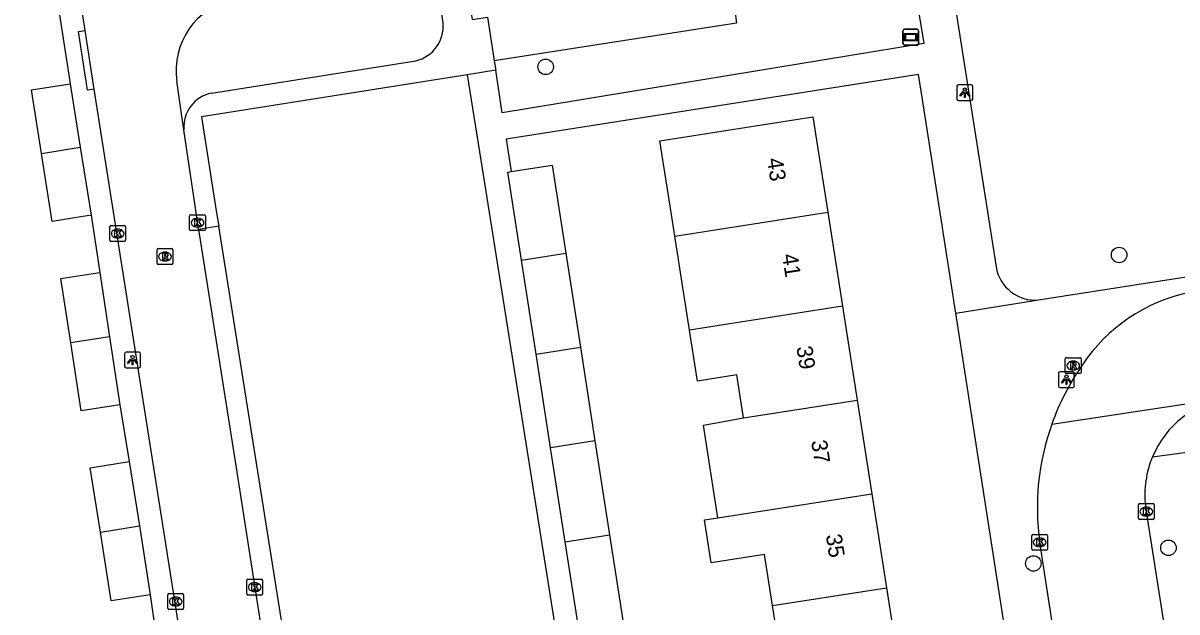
# Model space of a CAD drawing. Extents: x 160077 to 160945, y 386481 to 387498.
# Drawn here: x 160547.5 to 160620.3, y 387416.6 to 387453.8 of the extents above; entities that cross this region are included whole.
import ezdxf

# ---------------------------------------------------------------- set-up
doc = ezdxf.new("R2010")
doc.units = 0
for name, color, linetype in [('IMGEO_Boom', 7, 'Continuous'), ('IMGEO_Groenvoorziening', 7, 'Continuous'), ('IMGEO_Kolk', 7, 'Continuous'), ('IMGEO_Lichtpunt', 7, 'Continuous'), ('IMGEO_Pand', 7, 'Continuous'), ('IMGEO_Pand_nummerreeks', 7, 'Continuous'), ('IMGEO_Rijbaan_lokaal_open', 7, 'Continuous'), ('IMGEO_Rioolput', 7, 'Continuous'), ('IMGEO_Verklikker', 7, 'Continuous'), ('IMGEO_Voetpad_open', 7, 'Continuous')]:
    doc.layers.add(name, color=color, linetype=linetype)

msp = doc.modelspace()

# ---------------------------------------------------------------- linework, layer by layer
at = {"layer": 'IMGEO_Boom'}
for centre in [(160580.467, 387451.067), (160616.653, 387439.186), (160619.768, 387420.692), (160611.243, 387419.704)]:
    msp.add_circle(centre, 0.489, dxfattribs=at)
at = {"layer": 'IMGEO_Groenvoorziening'}
msp.add_lwpolyline([(160525.051, 387462.081), (160541.077, 387464.558), (160541.983, 387470.387), (160543.017, 387477.036), (160575.946, 387480.154), (160584.088, 387468.697), (160592.027, 387457.524), (160592.503, 387453.837), (160577.226, 387451.446)], dxfattribs=at)
at = {"layer": 'IMGEO_Kolk'}
for p, q in [((160557.998, 387440.804), (160557.998, 387441.656)), ((160558.073, 387441.73), (160558.925, 387441.73)), ((160558.999, 387441.656), (160558.999, 387440.804)), ((160552.962, 387440.113), (160552.962, 387440.965)), ((160553.037, 387441.039), (160553.889, 387441.039)), ((160553.963, 387440.965), (160553.963, 387440.113)), ((160558.509, 387440.95), (160558.484, 387440.95)), ((160558.486, 387441.51), (160558.511, 387441.51)), ((160553.473, 387440.259), (160553.448, 387440.259)), ((160553.45, 387440.819), (160553.475, 387440.819)), ((160558.925, 387440.73), (160558.073, 387440.73)), ((160553.889, 387440.039), (160553.037, 387440.039)), ((160617.871, 387422.556), (160617.871, 387423.408)), ((160617.946, 387423.482), (160618.798, 387423.482)), ((160618.872, 387423.408), (160618.872, 387422.556)), ((160618.382, 387422.702), (160618.357, 387422.702)), ((160618.359, 387423.262), (160618.384, 387423.262)), ((160618.798, 387422.482), (160617.946, 387422.482)), ((160611.139, 387420.614), (160611.139, 387421.466)), ((160611.214, 387421.54), (160612.066, 387421.54)), ((160611.627, 387421.32), (160611.652, 387421.32)), ((160612.14, 387421.466), (160612.14, 387420.614)), ((160612.066, 387420.54), (160611.214, 387420.54)), ((160611.65, 387420.76), (160611.625, 387420.76)), ((160561.606, 387417.779), (160561.606, 387418.631)), ((160561.681, 387418.705), (160562.533, 387418.705)), ((160562.094, 387418.485), (160562.119, 387418.485)), ((160562.607, 387418.631), (160562.607, 387417.779)), ((160556.621, 387416.871), (160556.621, 387417.723)), ((160556.696, 387417.797), (160557.548, 387417.797)), ((160557.109, 387417.577), (160557.134, 387417.577)), ((160557.622, 387417.723), (160557.622, 387416.871)), ((160562.533, 387417.705), (160561.681, 387417.705)), ((160562.117, 387417.925), (160562.092, 387417.925)), ((160557.132, 387417.017), (160557.107, 387417.017)), ((160557.548, 387416.797), (160556.696, 387416.797))]:
    msp.add_line(p, q, dxfattribs=at)
for points in [[(160557.998, 387440.804), (160557.998, 387441.656)], [(160558.073, 387441.73), (160558.925, 387441.73)], [(160558.999, 387441.656), (160558.999, 387440.804)], [(160552.962, 387440.113), (160552.962, 387440.965)], [(160553.037, 387441.039), (160553.889, 387441.039)], [(160553.963, 387440.965), (160553.963, 387440.113)], [(160558.319, 387441.43), (160558.442, 387441.43), (160558.442, 387441.279), (160558.572, 387441.43), (160558.736, 387441.43), (160558.59, 387441.279), (160558.743, 387441.03), (160558.591, 387441.03), (160558.506, 387441.194), (160558.442, 387441.127), (160558.442, 387441.03), (160558.319, 387441.03), (160558.319, 387441.43)], [(160553.283, 387440.739), (160553.406, 387440.739), (160553.406, 387440.588), (160553.536, 387440.739), (160553.7, 387440.739), (160553.554, 387440.588), (160553.707, 387440.339), (160553.555, 387440.339), (160553.47, 387440.503), (160553.406, 387440.436), (160553.406, 387440.339), (160553.283, 387440.339), (160553.283, 387440.739)], [(160558.925, 387440.73), (160558.073, 387440.73)], [(160553.889, 387440.039), (160553.037, 387440.039)], [(160617.871, 387422.556), (160617.871, 387423.408)], [(160617.946, 387423.482), (160618.798, 387423.482)], [(160618.872, 387423.408), (160618.872, 387422.556)], [(160618.192, 387423.182), (160618.315, 387423.182), (160618.315, 387423.031), (160618.445, 387423.182), (160618.609, 387423.182), (160618.463, 387423.031), (160618.616, 387422.782), (160618.464, 387422.782), (160618.379, 387422.946), (160618.315, 387422.879), (160618.315, 387422.782), (160618.192, 387422.782), (160618.192, 387423.182)], [(160618.798, 387422.482), (160617.946, 387422.482)], [(160611.139, 387420.614), (160611.139, 387421.466)], [(160611.214, 387421.54), (160612.066, 387421.54)], [(160611.46, 387421.24), (160611.583, 387421.24), (160611.583, 387421.089), (160611.713, 387421.24), (160611.877, 387421.24), (160611.731, 387421.089), (160611.884, 387420.84), (160611.732, 387420.84), (160611.647, 387421.004), (160611.583, 387420.937), (160611.583, 387420.84), (160611.46, 387420.84), (160611.46, 387421.24)], [(160612.14, 387421.466), (160612.14, 387420.614)], [(160612.066, 387420.54), (160611.214, 387420.54)], [(160561.606, 387417.779), (160561.606, 387418.631)], [(160561.681, 387418.705), (160562.533, 387418.705)], [(160561.927, 387418.405), (160562.05, 387418.405), (160562.05, 387418.254), (160562.18, 387418.405), (160562.344, 387418.405), (160562.198, 387418.254), (160562.351, 387418.005), (160562.199, 387418.005), (160562.114, 387418.169), (160562.05, 387418.102), (160562.05, 387418.005), (160561.927, 387418.005), (160561.927, 387418.405)], [(160562.607, 387418.631), (160562.607, 387417.779)], [(160556.621, 387416.871), (160556.621, 387417.723)], [(160556.696, 387417.797), (160557.548, 387417.797)], [(160557.622, 387417.723), (160557.622, 387416.871)], [(160562.533, 387417.705), (160561.681, 387417.705)], [(160556.942, 387417.497), (160557.065, 387417.497), (160557.065, 387417.346), (160557.195, 387417.497), (160557.359, 387417.497), (160557.213, 387417.346), (160557.366, 387417.097), (160557.214, 387417.097), (160557.129, 387417.261), (160557.065, 387417.194), (160557.065, 387417.097), (160556.942, 387417.097), (160556.942, 387417.497)], [(160557.548, 387416.797), (160556.696, 387416.797)]]:
    msp.add_lwpolyline(points, dxfattribs=at)
for centre, start, end in [((160558.075, 387441.654), 91.55205, 178.44795), ((160558.075, 387441.654), 91.55205, 178.44795), ((160558.923, 387441.654), 1.55205, 88.44795), ((160558.923, 387441.654), 1.55205, 88.44795), ((160553.039, 387440.963), 91.55205, 178.44795), ((160553.039, 387440.963), 91.55205, 178.44795), ((160553.887, 387440.963), 1.55205, 88.44795), ((160553.887, 387440.963), 1.55205, 88.44795), ((160558.075, 387440.806), 181.55205, 268.44795), ((160558.075, 387440.806), 181.55205, 268.44795), ((160558.923, 387440.806), 271.55205, 358.44795), ((160558.923, 387440.806), 271.55205, 358.44795), ((160553.039, 387440.115), 181.55205, 268.44795), ((160553.039, 387440.115), 181.55205, 268.44795), ((160553.887, 387440.115), 271.55205, 358.44795), ((160553.887, 387440.115), 271.55205, 358.44795), ((160617.948, 387423.406), 91.55205, 178.44795), ((160617.948, 387423.406), 91.55205, 178.44795), ((160618.796, 387423.406), 1.55205, 88.44795), ((160618.796, 387423.406), 1.55205, 88.44795), ((160617.948, 387422.558), 181.55205, 268.44795), ((160617.948, 387422.558), 181.55205, 268.44795), ((160618.796, 387422.558), 271.55205, 358.44795), ((160618.796, 387422.558), 271.55205, 358.44795), ((160611.216, 387421.464), 91.55205, 178.44795), ((160611.216, 387421.464), 91.55205, 178.44795), ((160612.064, 387421.464), 1.55205, 88.44795), ((160612.064, 387421.464), 1.55205, 88.44795), ((160611.216, 387420.616), 181.55205, 268.44795), ((160611.216, 387420.616), 181.55205, 268.44795), ((160612.064, 387420.616), 271.55205, 358.44795), ((160612.064, 387420.616), 271.55205, 358.44795), ((160561.683, 387418.629), 91.55205, 178.44795), ((160561.683, 387418.629), 91.55205, 178.44795), ((160562.531, 387418.629), 1.55205, 88.44795), ((160562.531, 387418.629), 1.55205, 88.44795), ((160556.698, 387417.721), 91.55205, 178.44795), ((160556.698, 387417.721), 91.55205, 178.44795), ((160557.546, 387417.721), 1.55205, 88.44795), ((160557.546, 387417.721), 1.55205, 88.44795), ((160561.683, 387417.781), 181.55205, 268.44795), ((160561.683, 387417.781), 181.55205, 268.44795), ((160562.531, 387417.781), 271.55205, 358.44795), ((160562.531, 387417.781), 271.55205, 358.44795), ((160556.698, 387416.873), 181.55205, 268.44795), ((160556.698, 387416.873), 181.55205, 268.44795), ((160557.546, 387416.873), 271.55205, 358.44795), ((160557.546, 387416.873), 271.55205, 358.44795)]:
    msp.add_arc(centre, 0.0765, start, end, dxfattribs=at)
for centre, major_axis, ratio, start_param, end_param in [((160558.485, 387441.23), (-0.387, 0.002), 0.722429, 4.712389, 7.853982), ((160558.51, 387441.23), (-0.39, 0.002), 0.717154, 1.570796, 4.712389), ((160553.449, 387440.539), (-0.387, 0.002), 0.722429, 4.712389, 7.853982), ((160553.474, 387440.539), (-0.39, 0.002), 0.717154, 1.570796, 4.712389), ((160618.358, 387422.982), (-0.387, 0.002), 0.722429, 4.712389, 7.853982), ((160618.383, 387422.982), (-0.39, 0.002), 0.717154, 1.570796, 4.712389), ((160611.626, 387421.04), (-0.387, 0.002), 0.722429, 4.712389, 7.853982), ((160611.651, 387421.04), (-0.39, 0.002), 0.717154, 1.570796, 4.712389), ((160562.093, 387418.205), (-0.387, 0.002), 0.722429, 4.712389, 7.853982), ((160562.118, 387418.205), (-0.39, 0.002), 0.717154, 1.570796, 4.712389), ((160557.108, 387417.297), (-0.387, 0.002), 0.722429, 4.712389, 7.853982), ((160557.133, 387417.297), (-0.39, 0.002), 0.717154, 1.570796, 4.712389)]:
    msp.add_ellipse(centre, major_axis=major_axis, ratio=ratio, start_param=start_param, end_param=end_param, dxfattribs=at)
at = {"layer": 'IMGEO_Lichtpunt'}
for p, q in [((160606.421, 387449.841), (160606.421, 387449.034)), ((160606.421, 387449.841), (160606.421, 387449.034)), ((160607.323, 387449.936), (160606.515, 387449.936)), ((160607.323, 387449.936), (160606.515, 387449.936)), ((160607.417, 387449.034), (160607.417, 387449.841)), ((160607.417, 387449.034), (160607.417, 387449.841)), ((160606.515, 387448.94), (160607.323, 387448.94)), ((160606.515, 387448.94), (160607.323, 387448.94)), ((160553.9, 387432.95), (160553.9, 387432.143)), ((160553.9, 387432.95), (160553.9, 387432.143)), ((160554.802, 387433.045), (160553.994, 387433.045)), ((160554.802, 387433.045), (160553.994, 387433.045)), ((160554.896, 387432.143), (160554.896, 387432.95)), ((160554.896, 387432.143), (160554.896, 387432.95)), ((160553.994, 387432.049), (160554.802, 387432.049)), ((160553.994, 387432.049), (160554.802, 387432.049)), ((160612.832, 387431.72), (160612.832, 387430.913)), ((160612.832, 387431.72), (160612.832, 387430.913)), ((160613.734, 387431.815), (160612.926, 387431.815)), ((160613.734, 387431.815), (160612.926, 387431.815)), ((160613.828, 387430.913), (160613.828, 387431.72)), ((160613.828, 387430.913), (160613.828, 387431.72)), ((160612.926, 387430.819), (160613.734, 387430.819)), ((160612.926, 387430.819), (160613.734, 387430.819))]:
    msp.add_line(p, q, dxfattribs=at)
for points in [[(160606.795, 387449.505), (160606.834, 387449.477), (160606.646, 387449.215), (160606.608, 387449.242), (160606.795, 387449.505)], [(160606.897, 387449.457), (160606.944, 387449.457), (160606.944, 387449.135), (160606.897, 387449.135), (160606.897, 387449.457)], [(160607.007, 387449.477), (160607.045, 387449.504), (160607.232, 387449.242), (160607.193, 387449.214), (160607.007, 387449.477)], [(160554.274, 387432.614), (160554.313, 387432.586), (160554.125, 387432.324), (160554.087, 387432.351), (160554.274, 387432.614)], [(160554.376, 387432.566), (160554.423, 387432.566), (160554.423, 387432.244), (160554.376, 387432.244), (160554.376, 387432.566)], [(160554.486, 387432.586), (160554.524, 387432.613), (160554.711, 387432.351), (160554.672, 387432.323), (160554.486, 387432.586)], [(160613.206, 387431.384), (160613.245, 387431.356), (160613.057, 387431.094), (160613.019, 387431.121), (160613.206, 387431.384)], [(160613.308, 387431.336), (160613.355, 387431.336), (160613.355, 387431.014), (160613.308, 387431.014), (160613.308, 387431.336)], [(160613.418, 387431.356), (160613.456, 387431.383), (160613.643, 387431.121), (160613.604, 387431.093), (160613.418, 387431.356)]]:
    msp.add_lwpolyline(points, dxfattribs=at)
for centre in [(160606.92, 387449.639), (160554.399, 387432.748), (160613.331, 387431.518)]:
    msp.add_circle(centre, 0.0994, dxfattribs=at)
for centre, start, end in [((160606.515, 387449.841), 90, 180), ((160606.515, 387449.841), 90, 180), ((160607.323, 387449.841), 0, 90), ((160607.323, 387449.841), 0, 90), ((160606.515, 387449.034), 180, 270), ((160606.515, 387449.034), 180, 270), ((160607.323, 387449.034), 270, 0), ((160607.323, 387449.034), 270, 360), ((160553.994, 387432.95), 90, 180), ((160553.994, 387432.95), 90, 180), ((160554.802, 387432.95), 0, 90), ((160554.802, 387432.95), 0, 90), ((160553.994, 387432.143), 180, 270), ((160553.994, 387432.143), 180, 270), ((160554.802, 387432.143), 270, 0), ((160554.802, 387432.143), 270, 360), ((160612.926, 387431.72), 90, 180), ((160612.926, 387431.72), 90, 180), ((160613.734, 387431.72), 0, 90), ((160613.734, 387431.72), 0, 90), ((160612.926, 387430.913), 180, 270), ((160612.926, 387430.913), 180, 270), ((160613.734, 387430.913), 270, 0), ((160613.734, 387430.913), 270, 360)]:
    msp.add_arc(centre, 0.0946, start, end, dxfattribs=at)
at = {"layer": 'IMGEO_Pand'}
for points in [[(160575.523, 387450.574), (160558.743, 387447.909), (160559.684, 387441.983), (160559.841, 387440.996)], [(160575.523, 387450.574), (160576.464, 387444.648), (160591.839, 387347.839)], [(160548.65, 387445.599), (160548.012, 387449.608), (160550.458, 387450)], [(160550.458, 387450), (160551.097, 387445.985)], [(160588.617, 387440.371), (160588.447, 387441.461), (160587.676, 387446.401), (160597.337, 387447.91), (160598.278, 387441.88)], [(160548.65, 387445.599), (160551.097, 387445.985)], [(160551.097, 387445.985), (160551.779, 387441.696)], [(160551.779, 387441.696), (160549.333, 387441.306), (160548.65, 387445.599)], [(160578.3, 387444.458), (160580.872, 387444.858), (160581.736, 387439.296)], [(160578.938, 387438.859), (160578.074, 387444.423), (160578.3, 387444.458)], [(160588.617, 387440.371), (160598.278, 387441.88)], [(160598.278, 387441.88), (160599.204, 387435.952)], [(160577.677, 387328.687), (160559.841, 387440.996)], [(160589.543, 387434.443), (160588.617, 387440.371)], [(160578.938, 387438.859), (160581.736, 387439.296)], [(160579.859, 387432.93), (160578.938, 387438.859)], [(160581.736, 387439.296), (160582.657, 387433.367)], [(160550.497, 387433.639), (160549.873, 387437.709), (160552.323, 387438.084)], [(160552.323, 387438.084), (160552.945, 387434.025)], [(160599.204, 387435.952), (160589.543, 387434.443)], [(160599.204, 387435.952), (160600.129, 387430.024)], [(160592.954, 387428.903), (160592.532, 387431.606), (160590.046, 387431.218), (160589.543, 387434.443)], [(160552.945, 387434.025), (160550.497, 387433.639)], [(160553.604, 387429.726), (160551.154, 387429.35), (160550.497, 387433.639)], [(160552.945, 387434.025), (160553.604, 387429.726)], [(160579.859, 387432.93), (160582.657, 387433.367)], [(160580.78, 387427.001), (160579.859, 387432.93)], [(160582.657, 387433.367), (160583.578, 387427.438)], [(160592.954, 387428.903), (160600.129, 387430.024)], [(160600.129, 387430.024), (160601.054, 387424.096)], [(160591.336, 387422.579), (160590.423, 387428.43), (160592.954, 387428.903)], [(160583.578, 387427.438), (160580.78, 387427.001)], [(160583.578, 387427.438), (160584.498, 387421.512)], [(160581.701, 387421.075), (160580.78, 387427.001)], [(160552.366, 387421.682), (160551.721, 387425.746), (160554.181, 387426.137)], [(160554.181, 387426.137), (160554.827, 387422.07)], [(160591.336, 387422.579), (160601.054, 387424.096)], [(160601.054, 387424.096), (160601.98, 387418.168)], [(160552.366, 387421.682), (160554.827, 387422.07)], [(160554.827, 387422.07), (160555.516, 387417.73)], [(160594.783, 387417.045), (160594.279, 387420.273), (160590.918, 387419.748), (160590.497, 387422.448), (160591.336, 387422.579)], [(160555.516, 387417.73), (160553.056, 387417.34), (160552.366, 387421.682)], [(160581.701, 387421.075), (160584.498, 387421.512)], [(160584.498, 387421.512), (160585.419, 387415.584)], [(160582.621, 387415.147), (160581.701, 387421.075)], [(160594.783, 387417.045), (160601.98, 387418.168)], [(160601.98, 387418.168), (160602.905, 387412.24)], [(160593.199, 387410.725), (160592.704, 387413.897), (160595.213, 387414.289), (160594.783, 387417.045)]]:
    msp.add_lwpolyline(points, dxfattribs=at)
at = {"layer": 'IMGEO_Rijbaan_lokaal_open'}
for points in [[(160551.403, 387453.359), (160549.245, 387467.288)], [(160551.976, 387449.649), (160551.403, 387453.359)], [(160571.264, 387326.474), (160566.063, 387360.17), (160551.976, 387449.649)], [(160557.641, 387447.096), (160557.387, 387448.84), (160557.198, 387450.169)], [(160558.566, 387440.793), (160558.469, 387441.409), (160558.34, 387442.295), (160557.641, 387447.096)], [(160558.566, 387440.793), (160560.933, 387425.732), (160566.779, 387388.194), (160571.754, 387356.264), (160576.092, 387327.919)], [(160612.403, 387428.493), (160623.505, 387430.178)], [(160618.318, 387423.36), (160618.371, 387422.985), (160624.877, 387381.437)], [(160618.109, 387380.11), (160617.91, 387381.338), (160614.175, 387404.637), (160611.642, 387421.037)]]:
    msp.add_lwpolyline(points, dxfattribs=at)
for centre, radius, start, end in [((160561.699, 387450.857), 4.554, 101.91703, 188.69614), ((160623.278, 387426.3), 10.741, 101.97674, 146.32845), ((160627.253, 387423.23), 15.755, 145.05236, 160.48513), ((160624.494, 387424.044), 6.214, 99.15994, 157.34518), ((160627.33, 387423.203), 15.837, 160.48509, 187.85943), ((160624.482, 387424.045), 6.202, 157.31195, 186.33922)]:
    msp.add_arc(centre, radius, start, end, dxfattribs=at)
at = {"layer": 'IMGEO_Rioolput'}
for p, q in [((160555.944, 387438.66), (160555.944, 387439.512)), ((160556.019, 387439.586), (160556.871, 387439.586)), ((160556.945, 387439.512), (160556.945, 387438.66)), ((160556.455, 387438.806), (160556.43, 387438.806)), ((160556.432, 387439.366), (160556.457, 387439.366)), ((160556.871, 387438.586), (160556.019, 387438.586)), ((160613.257, 387431.774), (160613.257, 387432.626)), ((160613.332, 387432.7), (160614.184, 387432.7)), ((160613.745, 387432.48), (160613.77, 387432.48)), ((160614.258, 387432.626), (160614.258, 387431.774)), ((160614.184, 387431.7), (160613.332, 387431.7)), ((160613.768, 387431.92), (160613.743, 387431.92))]:
    msp.add_line(p, q, dxfattribs=at)
for points in [[(160555.944, 387438.66), (160555.944, 387439.512)], [(160556.019, 387439.586), (160556.871, 387439.586)], [(160556.945, 387439.512), (160556.945, 387438.66)], [(160556.533, 387439.284), (160556.281, 387439.286), (160556.281, 387438.886)], [(160556.281, 387438.886), (160556.405, 387438.886), (160556.405, 387439.048), (160556.416, 387439.048)], [(160556.459, 387439.205), (160556.405, 387439.205), (160556.405, 387439.124)], [(160556.405, 387439.124), (160556.457, 387439.124)], [(160556.463, 387439.019), (160556.534, 387438.886), (160556.674, 387438.886), (160556.609, 387439.012)], [(160556.871, 387438.586), (160556.019, 387438.586)], [(160613.257, 387431.774), (160613.257, 387432.626)], [(160613.332, 387432.7), (160614.184, 387432.7)], [(160613.846, 387432.398), (160613.594, 387432.4), (160613.594, 387432)], [(160613.594, 387432), (160613.718, 387432), (160613.718, 387432.162), (160613.729, 387432.162)], [(160613.772, 387432.319), (160613.718, 387432.319), (160613.718, 387432.238)], [(160613.718, 387432.238), (160613.77, 387432.238)], [(160613.776, 387432.133), (160613.847, 387432), (160613.987, 387432), (160613.922, 387432.126)], [(160614.258, 387432.626), (160614.258, 387431.774)], [(160614.184, 387431.7), (160613.332, 387431.7)]]:
    msp.add_lwpolyline(points, dxfattribs=at)
for centre, radius, start, end in [((160556.021, 387439.51), 0.0765, 91.55205, 178.44795), ((160556.021, 387439.51), 0.0765, 91.55205, 178.44795), ((160556.869, 387439.51), 0.0765, 1.55205, 88.44795), ((160556.869, 387439.51), 0.0765, 1.55205, 88.44795), ((160556.415, 387438.995), 0.0533, 26.02933, 88.69889), ((160556.441, 387439.313), 0.19, 274.7715, 282.96867), ((160556.465, 387439.109), 0.0964, 77.00612, 93.18647), ((160556.479, 387439.166), 0.0378, 276.66336, 79.67722), ((160556.532, 387439.174), 0.109, 350.36119, 89.41601), ((160556.53, 387439.174), 0.112, 277.58423, 350.98172), ((160556.514, 387438.959), 0.108, 29.51342, 73.79051), ((160556.021, 387438.662), 0.0765, 181.55205, 268.44795), ((160556.021, 387438.662), 0.0765, 181.55205, 268.44795), ((160556.869, 387438.662), 0.0765, 271.55205, 358.44795), ((160556.869, 387438.662), 0.0765, 271.55205, 358.44795), ((160613.334, 387432.624), 0.0765, 91.55205, 178.44795), ((160613.334, 387432.624), 0.0765, 91.55205, 178.44795), ((160613.728, 387432.109), 0.0533, 26.02933, 88.69889), ((160613.754, 387432.427), 0.19, 274.7715, 282.96867), ((160613.778, 387432.223), 0.0964, 77.00612, 93.18647), ((160613.792, 387432.28), 0.0378, 276.66336, 79.67722), ((160613.845, 387432.288), 0.109, 350.36119, 89.41601), ((160613.843, 387432.288), 0.112, 277.58423, 350.98172), ((160613.827, 387432.073), 0.108, 29.51342, 73.79051), ((160614.182, 387432.624), 0.0765, 1.55205, 88.44795), ((160614.182, 387432.624), 0.0765, 1.55205, 88.44795), ((160613.334, 387431.776), 0.0765, 181.55205, 268.44795), ((160613.334, 387431.776), 0.0765, 181.55205, 268.44795), ((160614.182, 387431.776), 0.0765, 271.55205, 358.44795), ((160614.182, 387431.776), 0.0765, 271.55205, 358.44795)]:
    msp.add_arc(centre, radius, start, end, dxfattribs=at)
for centre, major_axis, ratio, start_param, end_param in [((160556.431, 387439.086), (-0.387, 0.002), 0.722429, 4.712389, 7.853982), ((160556.456, 387439.086), (-0.39, 0.002), 0.717154, 1.570796, 4.712389), ((160613.744, 387432.2), (-0.387, 0.002), 0.722429, 4.712389, 7.853982), ((160613.769, 387432.2), (-0.39, 0.002), 0.717154, 1.570796, 4.712389)]:
    msp.add_ellipse(centre, major_axis=major_axis, ratio=ratio, start_param=start_param, end_param=end_param, dxfattribs=at)
at = {"layer": 'IMGEO_Verklikker'}
for p, q in [((160603.01, 387452.548), (160603.01, 387453.348)), ((160603.01, 387453.348), (160603.01, 387452.548)), ((160603.11, 387453.448), (160603.9, 387453.448)), ((160603.9, 387453.448), (160603.11, 387453.448)), ((160604, 387453.348), (160604, 387452.548)), ((160604, 387452.548), (160604, 387453.348)), ((160603.9, 387452.448), (160603.11, 387452.448)), ((160603.11, 387452.448), (160603.9, 387452.448))]:
    msp.add_line(p, q, dxfattribs=at)
for points in [[(160603.111, 387453.18), (160603.899, 387453.18), (160603.899, 387452.716), (160603.111, 387452.716), (160603.111, 387453.18)], [(160603.176, 387453.115), (160603.176, 387452.781), (160603.834, 387452.781), (160603.834, 387453.115), (160603.176, 387453.115)]]:
    msp.add_lwpolyline(points, dxfattribs=at)
for centre, start, end in [((160603.11, 387453.348), 90, 180), ((160603.11, 387453.348), 90, 180), ((160603.9, 387453.348), 0, 90), ((160603.9, 387453.348), 360, 90), ((160603.11, 387452.548), 180, 270), ((160603.11, 387452.548), 180, 270), ((160603.9, 387452.548), 270, 0), ((160603.9, 387452.548), 270, 0)]:
    msp.add_arc(centre, 0.1, start, end, dxfattribs=at)
at = {"layer": 'IMGEO_Voetpad_open'}
for points in [[(160598.969, 387485.166), (160599.864, 387479.342), (160601.786, 387467.986), (160604.327, 387452.552), (160577.727, 387448.173), (160577.315, 387450.866)], [(160601.448, 387485.066), (160602.326, 387479.554), (160604.266, 387467.887), (160608.89, 387438.447)], [(160573.125, 387471.025), (160573.427, 387469.125), (160575.821, 387454.051), (160576.803, 387454.215), (160577.226, 387451.446)], [(160549.221, 387457.999), (160549.973, 387453.135), (160550.458, 387450)], [(160573.993, 387453.834), (160573.493, 387457.322)], [(160551.976, 387449.649), (160551.556, 387449.586), (160550.984, 387453.296), (160551.403, 387453.359)], [(160559.376, 387449.407), (160572.274, 387451.455)], [(160577.226, 387451.446), (160577.315, 387450.866)], [(160577.315, 387450.866), (160575.523, 387450.574)], [(160606.344, 387435.512), (160604.247, 387449.015), (160604.003, 387450.575), (160577.982, 387446.504), (160578.3, 387444.458)], [(160551.779, 387441.696), (160552.323, 387438.084)], [(160559.841, 387440.996), (160558.566, 387440.793)], [(160611.577, 387436.343), (160621.84, 387437.953)], [(160606.344, 387435.512), (160611.577, 387436.343)], [(160617.393, 387364.36), (160606.344, 387435.512)], [(160553.604, 387429.726), (160554.181, 387426.137)], [(160618.76, 387426.437), (160623.882, 387427.131)], [(160555.516, 387417.73), (160556.017, 387414.166)]]:
    msp.add_lwpolyline(points, dxfattribs=at)
for centre, radius, start, end in [((160571.769, 387453.63), 2.233, 283.06076, 5.23756), ((160559.807, 387447.277), 2.173, 101.43068, 184.77401), ((160611.363, 387438.838), 2.504, 188.97627, 274.89976)]:
    msp.add_arc(centre, radius, start, end, dxfattribs=at)

# ---------------------------------------------------------------- texts
at = {"layer": 'IMGEO_Pand_nummerreeks'}
for s, p in [('43', (160594.432, 387445.25)), ('41', (160595.377, 387439.197)), ('39', (160596.287, 387433.367)), ('37', (160597.215, 387427.425)), ('35', (160598.142, 387421.484))]:
    msp.add_text(s, height=1, rotation=278.87211, dxfattribs=at).set_placement(p)

doc.saveas('drawing.dxf')
